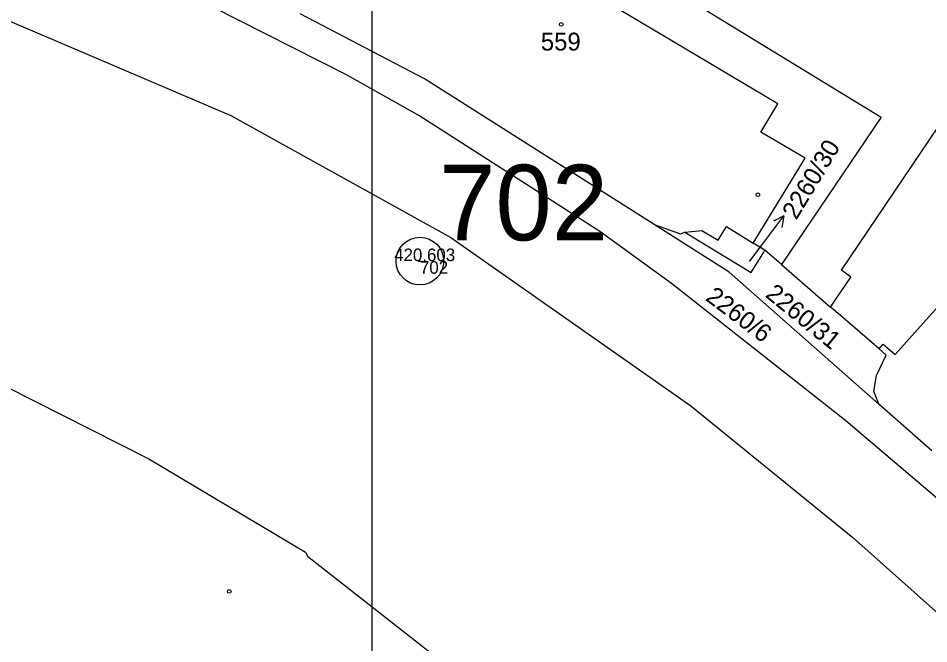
# Model space of a CAD drawing. Extents: x -667048 to -665920, y -1108425 to -1107247.
# Drawn here: x -666872 to -666785.4, y -1107407.4 to -1107347.8 of the extents above; entities that cross this region are included whole.
import ezdxf

# ---------------------------------------------------------------- set-up
doc = ezdxf.new("R2010")
doc.units = 0
for name, color, linetype in [('Default', 7, 'Continuous'), ('Hranice parcel', 7, 'Continuous'), ('Parcelní čísla', 7, 'Continuous'), ('Pop_ PČ_ popisy', 7, 'Continuous'), ('Vrstva 1', 7, 'Continuous'), ('Vrstva 2', 7, 'Continuous'), ('Vrstva 60', 7, 'Continuous'), ('Vrstva 61', 7, 'Continuous'), ('Značky budov', 7, 'Continuous')]:
    doc.layers.add(name, color=color, linetype=linetype)

# ---------------------------------------------------------------- blocks, each defined once
blk = doc.blocks.new('4.021')
at = {"layer": 'Default'}
blk.add_circle((-7, 1), 175, dxfattribs=at)
blk = doc.blocks.new('10291')
at = {"layer": 'Default'}
for p, q in [((0, 3001), (-500, 2001)), ((0, 1), (0, 3001)), ((0, 3001), (500, 2001))]:
    blk.add_line(p, q, dxfattribs=at)

msp = doc.modelspace()

# ---------------------------------------------------------------- linework, layer by layer
at = {"layer": 'Hranice parcel'}
for points in [[(-666914.82, -1107333.06), (-666908.74, -1107334.43), (-666905.84, -1107335.08), (-666891.95, -1107339.94), (-666851.81, -1107357.1), (-666830.89, -1107368.72), (-666808.07, -1107384.76), (-666792.66, -1107397.28), (-666774.87, -1107413.14), (-666760.36, -1107427.5), (-666748.63, -1107440.62), (-666736.58, -1107455.67), (-666731.43, -1107463.41), (-666717.64, -1107484.31), (-666709.65, -1107496.94)], [(-666802.13, -1107369.26), (-666797.19, -1107361.18), (-666801.4, -1107358.68), (-666799.78, -1107355.98), (-666835.11, -1107334.96), (-666836.4, -1107334.2), (-666842.42, -1107343.92), (-666842.98, -1107343.64)], [(-666823.36, -1107336.83), (-666789.95, -1107357.28), (-666799.44, -1107371.3)], [(-666683.99, -1107517.16), (-666734.88, -1107443.83), (-666739.56, -1107437.74), (-666744.57, -1107431.79), (-666763.51, -1107413.08), (-666776.63, -1107400.64), (-666782.75, -1107395.17), (-666793.33, -1107386.18), (-666809.9, -1107373.11), (-666816.72, -1107368.16), (-666833.93, -1107357.1), (-666840.83, -1107353.24), (-666853.59, -1107346.76), (-666868.25, -1107340.16)], [(-666811.55, -1107367.48), (-666833.4, -1107353.62), (-666845.22, -1107347.42)], [(-666794.78, -1107375.34), (-666794.41, -1107374.79), (-666792.85, -1107372.49), (-666793.74, -1107371.83), (-666782.8, -1107355.62), (-666778.65, -1107349.49)], [(-666790.16, -1107379.33), (-666789.77, -1107378.88), (-666788.63, -1107379.86), (-666775.94, -1107365.67), (-666771.5, -1107365.12), (-666741.55, -1107387.13)], [(-666790.17, -1107384.6), (-666804.41, -1107372.01), (-666811.55, -1107367.48)], [(-666811.55, -1107367.48), (-666809.06, -1107368.37), (-666808.62, -1107368.21)], [(-666808.62, -1107368.21), (-666807.03, -1107368.04), (-666805.48, -1107368.99), (-666804.68, -1107367.69), (-666802.13, -1107369.26)], [(-666808.62, -1107368.21), (-666802.33, -1107372.07), (-666801.12, -1107370.11), (-666801.02, -1107369.94)], [(-666801.02, -1107369.94), (-666802.13, -1107369.26)], [(-666799.44, -1107371.3), (-666801.02, -1107369.94)], [(-666799.44, -1107371.3), (-666796.97, -1107373.44), (-666794.78, -1107375.34)], [(-666790.16, -1107379.33), (-666794.27, -1107375.78), (-666794.78, -1107375.34)], [(-666882.84, -1107379.32), (-666873.3, -1107382.87), (-666859.63, -1107389.8), (-666844.72, -1107398.67), (-666844.48, -1107399.11), (-666844.08, -1107399.42), (-666833.53, -1107407.7), (-666832.41, -1107408.58), (-666819.89, -1107418.42), (-666818.78, -1107419.28), (-666815.21, -1107422.09), (-666808.14, -1107429.19), (-666803.72, -1107434.01), (-666799.15, -1107440.02), (-666799.37, -1107440.64), (-666800.17, -1107442.88), (-666801.3, -1107445.23), (-666801.72, -1107446.09), (-666802.21, -1107447.25)], [(-666790.17, -1107384.6), (-666790.66, -1107383.35), (-666790.39, -1107381.87), (-666789.48, -1107379.92), (-666790.16, -1107379.33)], [(-666785.15, -1107389.03), (-666790.17, -1107384.6)]]:
    msp.add_lwpolyline(points, dxfattribs=at)
at = {"layer": 'Pop_ PČ_ popisy'}
msp.add_lwpolyline([(-666802.48, -1107371.02), (-666801.02, -1107369.06)], dxfattribs=at)
at = {"layer": 'Vrstva 1'}
msp.add_line((-666833.982, -1107370.973), (-666833.682, -1107370.973), dxfattribs=at)
msp.add_circle((-666833.832, -1107370.973), 2.268, dxfattribs=at)
at = {"layer": 'Vrstva 2'}
msp.add_lwpolyline([(-666838.388, -1107343.373), (-666244.388, -1107343.373), (-666244.388, -1108183.373), (-666838.388, -1108183.373)], close=True, dxfattribs=at)
at = {"layer": 'Vrstva 60'}
msp.add_line((-666833.832, -1107370.973), (-666833.832, -1107370.973), dxfattribs=at)

# ---------------------------------------------------------------- block references
at = {"layer": 'Pop_ PČ_ popisy', "xscale": 0.0010000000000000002, "yscale": 0.001, "rotation": -37.000000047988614}
msp.add_blockref('10291', (-666801.02, -1107369.06), dxfattribs=at)
at = {"layer": 'Značky budov', "xscale": 0.0010000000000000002, "yscale": 0.0010000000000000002}
for p in [(-666820.39, -1107348.44), (-666801.68, -1107364.65), (-666851.97, -1107402.42)]:
    msp.add_blockref('4.021', p, dxfattribs=at)

# ---------------------------------------------------------------- texts
at = {"layer": 'Parcelní čísla'}
msp.add_text('559', height=1.7, dxfattribs=at).set_placement((-666822.33, -1107350.92))
for s, rotation, p in [('2260/30', 59, (-666798.03, -1107367.12)), ('2260/6', 323, (-666806.76, -1107374.63)), ('2260/31', 321, (-666801.07, -1107374.31))]:
    msp.add_text(s, height=1.7, rotation=rotation, dxfattribs=at).set_placement(p)
at = {"layer": 'Vrstva 1'}
msp.add_text('702', height=7.2, dxfattribs=at).set_placement((-666832, -1107369))
at = {"layer": 'Vrstva 60'}
msp.add_text('702', height=1.2, dxfattribs=at).set_placement((-666833.832, -1107372.173))
at = {"layer": 'Vrstva 61'}
msp.add_text('420.603', height=1.2, dxfattribs=at).set_placement((-666836.284, -1107370.973))

doc.saveas('drawing.dxf')
